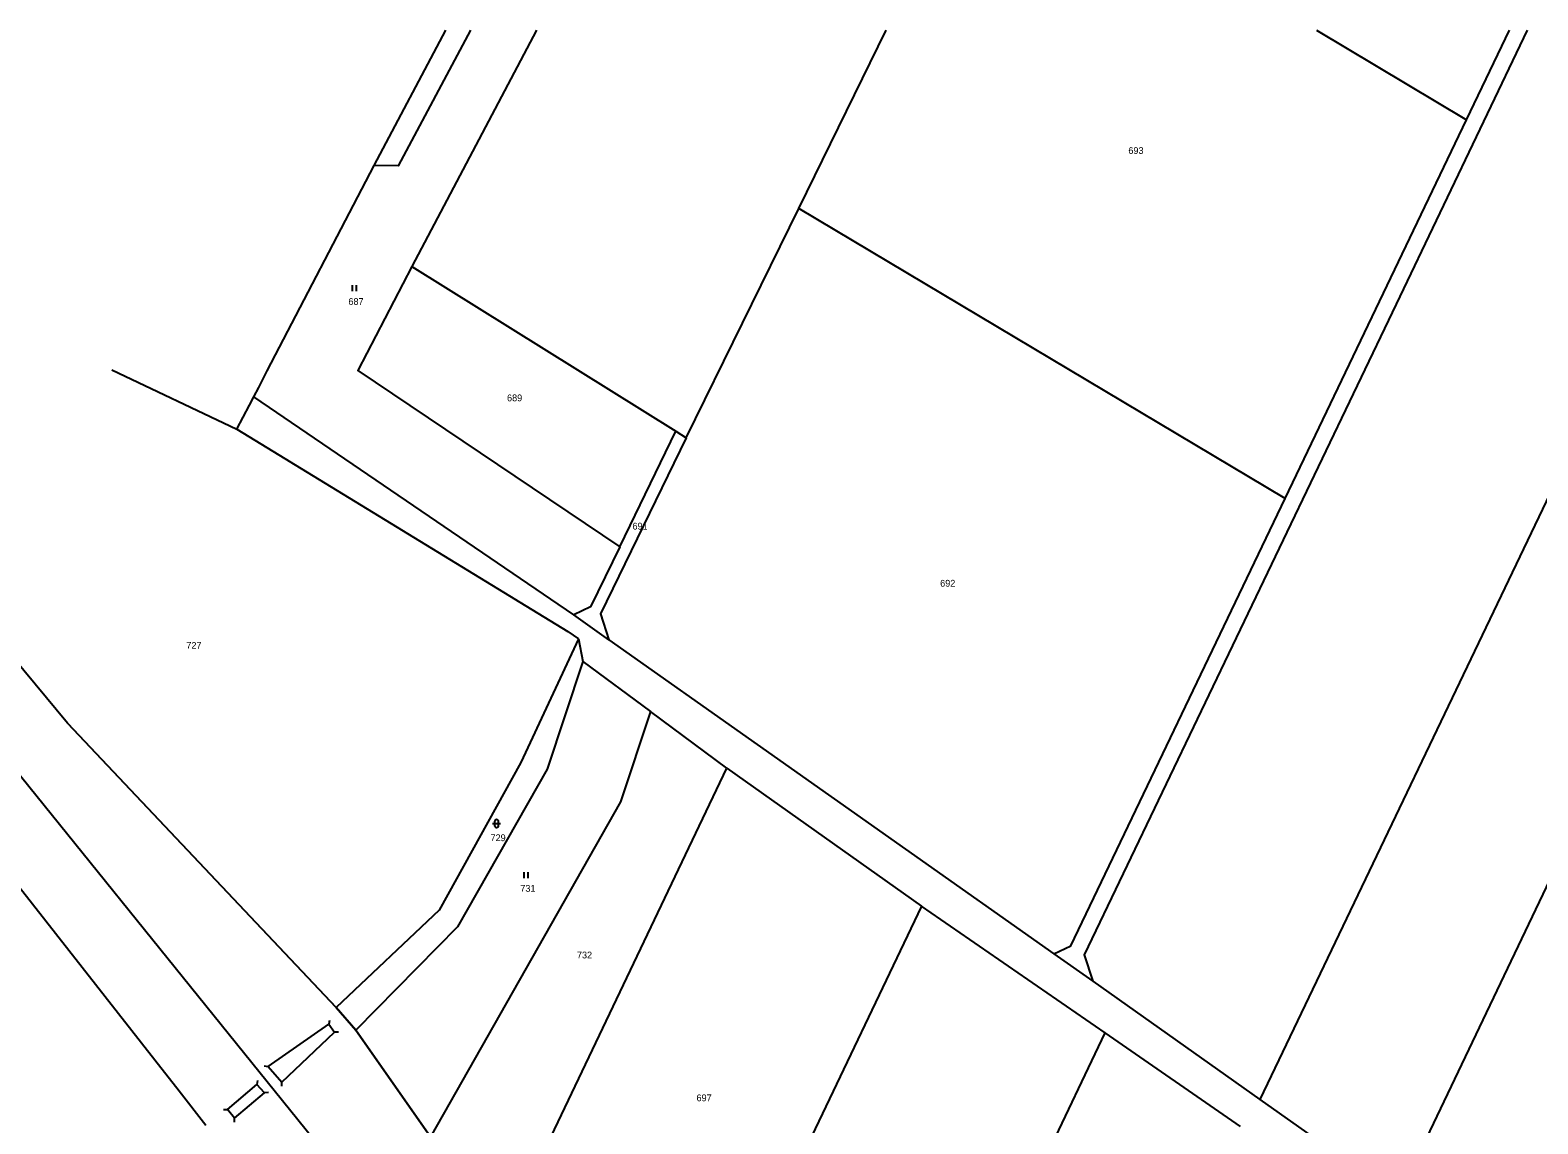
# Model space of a CAD drawing. Extents: x -504601 to -503665, y -1079870 to -1078626.
# Drawn here: x -504268.5 to -503891.4, y -1079148.4 to -1078875 of the extents above; entities that cross this region are included whole.
import ezdxf

# ---------------------------------------------------------------- set-up
doc = ezdxf.new("R2010")
doc.units = 0
for name, color, linetype in [('Hranice parcel', 7, 'Continuous'), ('Parcelní čísla', 7, 'Continuous'), ('Vnitřní kresba', 7, 'Continuous'), ('Vrstva 54', 7, 'Continuous'), ('Značky kultur', 7, 'Continuous')]:
    doc.layers.add(name, color=color, linetype=linetype)

msp = doc.modelspace()

# ---------------------------------------------------------------- linework, layer by layer
at = {"layer": 'Hranice parcel'}
for p, q in [((-504182.41, -1078908.88), (-504164.51, -1078875.01)), ((-504076.26, -1078919.59), (-504054.37, -1078875.01)), ((-503946.76, -1078875.01), (-503909.28, -1078897.41)), ((-503909.28, -1078897.41), (-503898.55, -1078875.01)), ((-503954.64, -1078992.12), (-503909.28, -1078897.41)), ((-504104.41, -1078976.91), (-504076.26, -1078919.59)), ((-503954.64, -1078992.12), (-504076.26, -1078919.59)), ((-504172.99, -1078934.08), (-504106.96, -1078975.25)), ((-504248.02, -1078959.95), (-504216.74, -1078974.75)), ((-504212.53, -1078966.67), (-504211.31, -1078964.34)), ((-504213.62, -1078968.77), (-504212.53, -1078966.67)), ((-504132.52, -1079021.15), (-504212.53, -1078966.67)), ((-504216.74, -1078974.75), (-504213.62, -1078968.77)), ((-504121.02, -1079004.17), (-504106.96, -1078975.25)), ((-504106.96, -1078975.25), (-504104.41, -1078976.91)), ((-504237.3, -1079132.48), (-504335.24, -1079007.61)), ((-504123.75, -1079027.4), (-504132.52, -1079021.15)), ((-504131.37, -1079027.17), (-504130.21, -1079032.82)), ((-504123.75, -1079027.4), (-504012.46, -1079105.9)), ((-504130.21, -1079032.82), (-504113.31, -1079045.35)), ((-504094.24, -1079059.5), (-504113.31, -1079045.35)), ((-504150.39, -1079177.22), (-504094.24, -1079059.5)), ((-504094.24, -1079059.5), (-504045.55, -1079093.99)), ((-504045.55, -1079093.99), (-504109.47, -1079227.67)), ((-503999.6, -1079125.68), (-504045.55, -1079093.99)), ((-504012.46, -1079105.9), (-504002.73, -1079112.77)), ((-504002.73, -1079112.77), (-503960.91, -1079142.29)), ((-504187.04, -1079125.02), (-504191.97, -1079119.35)), ((-504168.33, -1079151.66), (-504187.04, -1079125.02)), ((-504070.38, -1079273.8), (-503999.6, -1079125.68)), ((-503965.74, -1079149.03), (-503999.6, -1079125.68)), ((-503960.91, -1079142.29), (-503926.36, -1079166.74))]:
    msp.add_line(p, q, dxfattribs=at)
for points in [[(-504158.31, -1078875.01), (-504176.41, -1078908.95), (-504182.41, -1078908.88)], [(-504141.85, -1078875.01), (-504172.99, -1078934.08)], [(-503894.08, -1078875.01), (-503926.89, -1078943.47), (-504004.86, -1079106.18), (-504002.73, -1079112.77)], [(-503832.99, -1078875.01), (-503883.7, -1078980.97), (-503960.91, -1079142.29)], [(-503787.07, -1078875.01), (-503845.26, -1078996.89), (-503926.36, -1079166.74)], [(-504211.31, -1078964.34), (-504209.15, -1078960.2), (-504182.41, -1078908.88)], [(-504172.99, -1078934.08), (-504186.53, -1078960.06), (-504121.02, -1079004.17)], [(-504191.97, -1079119.35), (-504259.1, -1079048.24), (-504304.84, -1078993.19), (-504309, -1078988.18), (-504326.93, -1078966.59)], [(-504216.74, -1078974.75), (-504134.02, -1079025.32), (-504131.37, -1079027.17)], [(-504048.32, -1079336.41), (-504164.13, -1079193.65), (-504189.98, -1079161.66), (-504303.4, -1079021.3), (-504338.19, -1078978.95)], [(-504104.41, -1078976.91), (-504125.84, -1079020.94), (-504123.75, -1079027.4)], [(-504012.46, -1079105.9), (-504008.21, -1079103.89), (-503954.64, -1078992.12)], [(-504121.02, -1079004.17), (-504128.3, -1079019.16), (-504132.52, -1079021.15)], [(-504131.37, -1079027.17), (-504145.76, -1079058.04), (-504166.2, -1079094.95), (-504191.97, -1079119.35)], [(-504130.21, -1079032.82), (-504139.18, -1079059.71), (-504161.6, -1079099.12), (-504187.04, -1079125.02)], [(-504113.31, -1079045.35), (-504120.83, -1079067.9), (-504168.33, -1079151.66)], [(-504224.49, -1079148.81), (-504231.2, -1079140.26), (-504237.3, -1079132.48)]]:
    msp.add_lwpolyline(points, dxfattribs=at)
at = {"layer": 'Vnitřní kresba'}
for p, q in [((-504193.56, -1079122.53), (-504193.73, -1079123.52)), ((-504208.92, -1079134.03), (-504193.73, -1079123.52)), ((-504205.52, -1079137.98), (-504192.37, -1079125.45)), ((-504193.73, -1079123.52), (-504192.37, -1079125.45)), ((-504191.37, -1079125.5), (-504192.37, -1079125.45)), ((-504209.91, -1079133.91), (-504208.92, -1079134.03)), ((-504208.92, -1079134.03), (-504205.52, -1079137.98)), ((-504211.57, -1079137.57), (-504211.76, -1079138.55)), ((-504219.12, -1079144.85), (-504211.76, -1079138.55)), ((-504217.33, -1079146.99), (-504209.84, -1079140.69)), ((-504209.84, -1079140.69), (-504211.76, -1079138.55)), ((-504208.84, -1079140.6), (-504209.84, -1079140.69)), ((-504205.5, -1079138.98), (-504205.52, -1079137.98)), ((-504220.12, -1079144.83), (-504219.12, -1079144.85)), ((-504217.33, -1079146.99), (-504219.12, -1079144.85)), ((-504217.33, -1079147.99), (-504217.33, -1079146.99))]:
    msp.add_line(p, q, dxfattribs=at)
at = {"layer": 'Vrstva 54'}
for points in [[(-503867.31, -1079481.6), (-503895.86, -1079458.07), (-503942.64, -1079419.51), (-503946.4, -1079416.88), (-503945.84, -1079414.89), (-503977.25, -1079388.9), (-504014.44, -1079358.14), (-504038.99, -1079330.47), (-504044.97, -1079331.7), (-504048.32, -1079336.41), (-504164.13, -1079193.65), (-504189.98, -1079161.66), (-504303.4, -1079021.3)], [(-504259.1, -1079048.24), (-504191.97, -1079119.35), (-504187.04, -1079125.02), (-504168.33, -1079151.66), (-504150.39, -1079177.22), (-504141.49, -1079189.89), (-504109.47, -1079227.67), (-504070.38, -1079273.8), (-504043.38, -1079305.66), (-504041.43, -1079307.47), (-504008.27, -1079338.19), (-503988.82, -1079356.2), (-503938.33, -1079402.97), (-503888.76, -1079443.21), (-503860.04, -1079466.37)]]:
    msp.add_lwpolyline(points, dxfattribs=at)
at = {"layer": 'Značky kultur'}
for p, q in [((-504187.88, -1078940.29), (-504187.88, -1078938.79)), ((-504186.88, -1078940.29), (-504186.88, -1078938.79)), ((-504152.83, -1079073.34), (-504150.83, -1079073.34)), ((-504152.33, -1079072.84), (-504152.33, -1079073.84)), ((-504151.33, -1079073.84), (-504151.33, -1079072.84)), ((-504144.89, -1079086.99), (-504144.89, -1079085.49)), ((-504143.89, -1079086.99), (-504143.89, -1079085.49))]:
    msp.add_line(p, q, dxfattribs=at)
for centre, start, end in [((-504151.83, -1079072.84), 0, 180), ((-504151.83, -1079073.84), 180, 359.9879)]:
    msp.add_arc(centre, 0.5, start, end, dxfattribs=at)

# ---------------------------------------------------------------- texts
at = {"layer": 'Parcelní čísla'}
for s, p in [('693', (-503993.83, -1078905.95)), ('687', (-504188.87, -1078943.69)), ('689', (-504149.2, -1078967.78)), ('691', (-504117.84, -1078999.85)), ('692', (-504040.89, -1079014.12)), ('727', (-504229.4, -1079029.66)), ('729', (-504153.33, -1079077.74)), ('731', (-504145.88, -1079090.39)), ('732', (-504131.72, -1079107.05)), ('697', (-504101.82, -1079142.76))]:
    msp.add_text(s, height=1.7, dxfattribs=at).set_placement(p)

doc.saveas('drawing.dxf')
